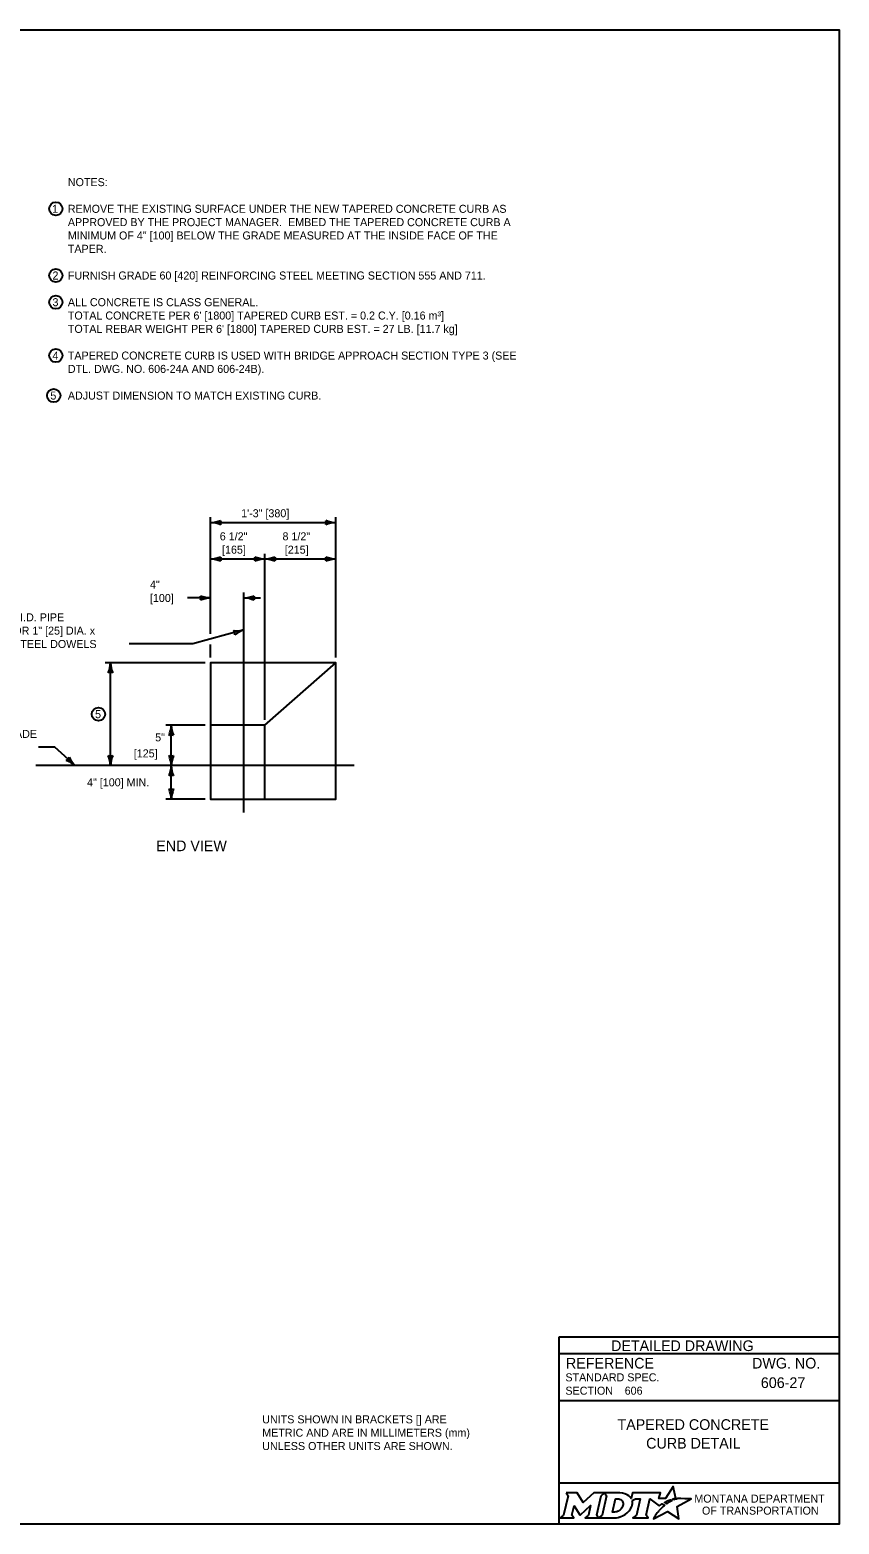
# Model space of a CAD drawing. Extents: x 49991.4 to 50021, y 49987.6 to 50011.4.
# Drawn here: x 50010.69 to 50016.75, y 49987.8 to 49999 of the extents above; entities that cross this region are included whole.
import ezdxf

# ---------------------------------------------------------------- set-up
doc = ezdxf.new("R2010")
doc.units = 0
for name, color, linetype in [('Default', 7, 'Continuous'), ('Level 1', 7, 'Continuous'), ('Level 2', 7, 'Continuous'), ('Level 3', 7, 'Continuous'), ('Level 4', 7, 'Continuous'), ('Level 5', 7, 'Continuous')]:
    doc.layers.add(name, color=color, linetype=linetype)

msp = doc.modelspace()

# ---------------------------------------------------------------- linework, layer by layer
at = {"layer": 'Default'}
for points in [[(50015.513, 49987.981), (50015.502, 49987.987), (50015.514, 49987.99), (50015.526, 49987.991), (50015.508, 49988.082), (50015.449, 49987.99), (50015.401, 49987.99), (50015.412, 49988.034), (50015.202, 49988.034), (50015.192, 49987.991), (50015.186, 49988)], [(50014.706, 49988.034), (50014.72, 49988.01), (50014.686, 49987.867), (50014.66, 49987.845), (50014.762, 49987.845), (50014.749, 49987.867), (50014.765, 49987.937), (50014.809, 49987.868), (50014.814, 49987.868), (50014.889, 49987.938), (50014.872, 49987.867), (50014.848, 49987.845), (50014.949, 49987.845), (50014.936, 49987.868), (50014.969, 49988.011)], [(50014.969, 49988.011), (50014.994, 49988.034), (50014.912, 49988.034), (50014.832, 49987.961), (50014.788, 49988.034), (50014.706, 49988.034)], [(50015.108, 49988.034), (50014.994, 49988.034), (50015.009, 49988.011), (50014.975, 49987.867), (50014.949, 49987.845), (50015.06, 49987.845)], [(50015.132, 49987.947), (50015.13, 49987.939), (50015.127, 49987.93), (50015.123, 49987.922), (50015.118, 49987.914), (50015.111, 49987.907), (50015.103, 49987.901), (50015.095, 49987.896), (50015.086, 49987.892), (50015.077, 49987.89), (50015.067, 49987.889), (50015.052, 49987.889), (50015.075, 49987.989), (50015.091, 49987.989), (50015.099, 49987.988), (50015.106, 49987.986), (50015.113, 49987.983), (50015.119, 49987.979), (50015.124, 49987.974), (50015.128, 49987.968), (50015.13, 49987.962), (50015.132, 49987.955), (50015.132, 49987.952), (50015.132, 49987.947)], [(50015.199, 49987.975), (50015.224, 49987.988), (50015.261, 49987.988), (50015.232, 49987.867), (50015.205, 49987.845), (50015.321, 49987.845), (50015.304, 49987.867), (50015.332, 49987.988), (50015.403, 49987.936), (50015.424, 49987.951), (50015.444, 49987.94)], [(50015.388, 49987.884), (50015.373, 49987.86), (50015.368, 49987.852), (50015.362, 49987.844), (50015.36, 49987.839), (50015.465, 49987.893), (50015.549, 49987.838), (50015.536, 49987.93), (50015.643, 49987.989), (50015.594, 49987.989), (50015.564, 49987.99), (50015.543, 49987.99), (50015.536, 49987.989), (50015.531, 49987.987), (50015.523, 49987.985), (50015.513, 49987.981)], [(50015.462, 49987.954), (50015.46, 49987.952), (50015.442, 49987.961), (50015.452, 49987.967), (50015.456, 49987.969), (50015.465, 49987.973), (50015.47, 49987.976), (50015.478, 49987.979), (50015.485, 49987.982), (50015.497, 49987.974), (50015.493, 49987.972), (50015.489, 49987.97), (50015.484, 49987.967), (50015.479, 49987.965), (50015.478, 49987.963), (50015.475, 49987.962), (50015.472, 49987.96), (50015.47, 49987.959), (50015.467, 49987.957), (50015.465, 49987.955), (50015.462, 49987.954)], [(50015.106, 49987.852), (50015.114, 49987.855), (50015.127, 49987.86), (50015.148, 49987.871)], [(50015.402, 49987.9), (50015.402, 49987.9)]]:
    msp.add_lwpolyline(points, dxfattribs=at)
for centre, radius, start, end in [((50015.131, 49987.955), 0.0709, 339.5329, 15.8582), ((50015.087, 49987.973), 0.118, 300.9103, 339.1383)]:
    msp.add_arc(centre, radius, start, end, dxfattribs=at)
for centre, major_axis, ratio, start_param, end_param in [((50015.106, 49987.986), (0.0834, -0.0037), 0.568097, 0.61298, 1.570796), ((50015.161, 49987.994), (0.0361, -0.0295), 0.469099, 1.225588, 1.570796), ((50015.06, 49987.993), (0, 0.148), 0.987302, 3.139398, 3.456847), ((50015.395, 49987.892), (-0.00694, -0.00806), 0.008222, 0, 3.137361), ((50015.412, 49987.911), (-0.0098, -0.0102), 0.016458, 3.141593, 6.279097), ((50015.433, 49987.93), (-0.0112, -0.0097), 0.021651, 3.157348, 6.283185)]:
    msp.add_ellipse(centre, major_axis=major_axis, ratio=ratio, start_param=start_param, end_param=end_param, dxfattribs=at)
at = {"layer": 'Level 1'}
for p, q in [((50012.449, 49993.787), (50012.981, 49994.255)), ((50012.449, 49993.787), (50012.042, 49993.787)), ((50012.449, 49993.484), (50012.449, 49993.787)), ((50013.117, 49993.484), (50010.732, 49993.484))]:
    msp.add_line(p, q, dxfattribs=at)
msp.add_lwpolyline([(49999.384, 49998.999), (50016.75, 49998.999), (50016.75, 49987.799), (49999.384, 49987.799)], close=True, dxfattribs=at)
msp.add_lwpolyline([(50012.981, 49993.484), (50012.981, 49994.255), (50012.042, 49994.255), (50012.042, 49993.484)], dxfattribs=at)
at = {"layer": 'Level 2'}
for centre in [(50010.883, 49997.658), (50010.883, 49997.158), (50010.883, 49996.958), (50010.883, 49996.558), (50010.867, 49996.258), (50011.202, 49993.87)]:
    msp.add_circle(centre, 0.05, dxfattribs=at)
at = {"layer": 'Level 3'}
for p, q in [((50012.042, 49994.472), (50012.042, 49995.346)), ((50012.981, 49994.295), (50012.981, 49995.346)), ((50012.042, 49995.306), (50012.981, 49995.306)), ((50012.449, 49995.033), (50012.042, 49995.033)), ((50012.449, 49993.827), (50012.449, 49995.073)), ((50012.981, 49995.033), (50012.449, 49995.033)), ((50012.042, 49994.741), (50011.869, 49994.741)), ((50012.292, 49994.741), (50012.416, 49994.741)), ((50012.292, 49994.501), (50011.908, 49994.396)), ((50011.908, 49994.396), (50011.432, 49994.396)), ((50012.042, 49994.295), (50012.042, 49994.392)), ((50012.002, 49994.255), (50011.252, 49994.255)), ((50011.292, 49993.484), (50011.292, 49994.255)), ((50012.002, 49993.787), (50011.708, 49993.787)), ((50011.748, 49993.484), (50011.748, 49993.787)), ((50010.876, 49993.622), (50010.752, 49993.622)), ((50011.028, 49993.484), (50010.876, 49993.622)), ((50011.748, 49993.233), (50011.748, 49993.484)), ((50012.002, 49993.233), (50011.708, 49993.233))]:
    msp.add_line(p, q, dxfattribs=at)
for centre, radius, start, end in [((50012.03, 49995.538), 0.233, 272.8273, 292.0772), ((50012.033, 49995.084), 0.222, 67.456, 87.6395), ((50012.17, 49995.306), 0.0548, 162.1388, 197.8612), ((50012.99, 49995.528), 0.222, 247.456, 267.6395), ((50012.853, 49995.306), 0.0548, 342.1388, 17.8612), ((50012.993, 49995.073), 0.233, 92.8273, 112.0772), ((50012.03, 49995.266), 0.233, 272.8273, 292.0772), ((50012.033, 49994.811), 0.222, 67.456, 87.6395), ((50012.17, 49995.033), 0.0548, 162.1388, 197.8612), ((50012.458, 49995.255), 0.222, 247.456, 267.6395), ((50012.321, 49995.033), 0.0548, 342.1388, 17.8612), ((50012.46, 49994.8), 0.233, 92.8273, 112.0772), ((50012.437, 49995.266), 0.233, 272.8273, 292.0772), ((50012.44, 49994.811), 0.222, 67.456, 87.6395), ((50012.577, 49995.033), 0.0548, 162.1388, 197.8612), ((50012.99, 49995.255), 0.222, 247.456, 267.6395), ((50012.853, 49995.033), 0.0548, 342.1388, 17.8612), ((50012.993, 49994.8), 0.233, 92.8273, 112.0772), ((50012.051, 49994.963), 0.222, 247.456, 267.6395), ((50011.914, 49994.741), 0.0548, 342.1388, 17.8612), ((50012.053, 49994.508), 0.233, 92.8273, 112.0772), ((50012.281, 49994.974), 0.233, 272.8273, 292.0772), ((50012.283, 49994.519), 0.222, 67.456, 87.6395), ((50012.421, 49994.741), 0.0548, 162.1388, 197.8612), ((50012.243, 49994.717), 0.222, 262.72, 282.9035), ((50012.169, 49994.467), 0.0548, 357.4028, 33.1251), ((50012.365, 49994.279), 0.233, 108.0913, 127.3411), ((50011.07, 49994.265), 0.222, 337.456, 357.6395), ((50011.525, 49994.267), 0.233, 182.8273, 202.0772), ((50011.292, 49994.127), 0.0548, 72.1388, 107.8612), ((50011.526, 49993.796), 0.222, 337.456, 357.6395), ((50011.98, 49993.799), 0.233, 182.8273, 202.0772), ((50011.748, 49993.659), 0.0548, 72.1388, 107.8612), ((50010.933, 49993.57), 0.0548, 300.0416, 335.764), ((50011.184, 49993.643), 0.222, 205.3588, 225.5423), ((50011.292, 49993.612), 0.0548, 252.1388, 287.8612), ((50011.059, 49993.472), 0.233, 2.8273, 22.0772), ((50011.514, 49993.475), 0.222, 157.456, 177.6395), ((50011.748, 49993.612), 0.0548, 252.1388, 287.8612), ((50011.515, 49993.472), 0.233, 2.8273, 22.0772), ((50011.97, 49993.475), 0.222, 157.456, 177.6395), ((50010.88, 49993.304), 0.233, 50.7301, 69.98), ((50011.526, 49993.493), 0.222, 337.456, 357.6395), ((50011.98, 49993.495), 0.233, 182.8273, 202.0772), ((50011.748, 49993.356), 0.0548, 72.1388, 107.8612), ((50011.748, 49993.362), 0.0548, 252.1388, 287.8612), ((50011.515, 49993.222), 0.233, 2.8273, 22.0772), ((50011.97, 49993.224), 0.222, 157.456, 177.6395)]:
    msp.add_arc(centre, radius, start, end, dxfattribs=at)
at = {"layer": 'Level 4'}
for points in [[(50012.042, 49993.484), (50012.042, 49993.233), (50012.449, 49993.233), (50012.449, 49993.484)], [(50012.449, 49993.233), (50012.981, 49993.233), (50012.981, 49993.484)]]:
    msp.add_lwpolyline(points, dxfattribs=at)
at = {"layer": 'Level 5'}
for p, q in [((50012.292, 49993.133), (50012.292, 49994.781)), ((50016.75, 49989.199), (50014.65, 49989.199)), ((50014.65, 49989.199), (50014.65, 49987.799)), ((50016.75, 49989.074), (50014.65, 49989.074)), ((50016.386, 49988.859), (50016.386, 49988.859)), ((50015.144, 49988.799), (50015.144, 49988.799)), ((50016.75, 49988.724), (50014.65, 49988.724)), ((50015.7, 49988.475), (50015.7, 49988.475)), ((50016.75, 49988.106), (50014.65, 49988.106))]:
    msp.add_line(p, q, dxfattribs=at)

# ---------------------------------------------------------------- texts
at = {"layer": 'Default'}
for s, p in [('MONTANA DEPARTMENT', (50015.666, 49987.96)), ('OF TRANSPORTATION', (50015.723, 49987.87))]:
    msp.add_text(s, height=0.06, dxfattribs=at).set_placement(p)
at = {"layer": 'Level 2'}
for s, height, p in [('NOTES:', 0.06, (50010.973, 49997.828)), ('1', 0.06, (50010.855, 49997.628)), ('APPROVED BY THE PROJECT MANAGER.  EMBED THE TAPERED CONCRETE CURB A', 0.06, (50010.973, 49997.528)), ('REMOVE THE EXISTING SURFACE UNDER THE NEW TAPERED CONCRETE CURB AS', 0.06, (50010.973, 49997.628)), ('MINIMUM OF 4" [100] BELOW THE GRADE MEASURED AT THE INSIDE FACE OF THE ', 0.06, (50010.973, 49997.428)), ('TAPER.', 0.06, (50010.973, 49997.328)), ('2', 0.06, (50010.858, 49997.128)), ('FURNISH GRADE 60 [420] REINFORCING STEEL MEETING SECTION 555 AND 711.', 0.06, (50010.973, 49997.128)), ('3', 0.06, (50010.858, 49996.928)), ('ALL CONCRETE IS CLASS GENERAL.  ', 0.06, (50010.973, 49996.928)), ("TOTAL CONCRETE PER 6' [1800] TAPERED CURB EST. = 0.2 C.Y. [0.16 m³]", 0.06, (50010.973, 49996.828)), ("TOTAL REBAR WEIGHT PER 6' [1800] TAPERED CURB EST. = 27 LB. [11.7 kg]", 0.06, (50010.973, 49996.728)), ('4', 0.06, (50010.858, 49996.528)), ('TAPERED CONCRETE CURB IS USED WITH BRIDGE APPROACH SECTION TYPE 3 (SEE', 0.06, (50010.973, 49996.528)), ('DTL. DWG. NO. 606-24A AND 606-24B).', 0.06, (50010.973, 49996.428)), ('5', 0.06, (50010.842, 49996.228)), ('ADJUST DIMENSION TO MATCH EXISTING CURB.', 0.06, (50010.973, 49996.228)), ('1\'-3" [380]', 0.06, (50012.271, 49995.346)), ('6 1/2"', 0.06, (50012.111, 49995.173)), ('8 1/2"', 0.06, (50012.581, 49995.173)), ('[165]', 0.06, (50012.128, 49995.073)), ('[215]', 0.06, (50012.598, 49995.073)), ('4"', 0.06, (50011.588, 49994.811)), ('[100]', 0.06, (50011.588, 49994.711)), ('¡ 1 1/2" [38] I.D. PIPE', 0.06, (50010.181, 49994.566)), ('SLEEVE FOR 1" [25] DIA. x', 0.06, (50010.181, 49994.466)), ('3\'-0" [915] STEEL DOWELS', 0.06, (50010.181, 49994.366)), ('5', 0.06, (50011.177, 49993.84)), ('FINISHED GRADE', 0.06, (50010.06, 49993.692)), ('5"', 0.06, (50011.627, 49993.666)), ('[125]', 0.06, (50011.467, 49993.546)), ('4" [100] MIN.', 0.06, (50011.117, 49993.329)), ('END VIEW', 0.08, (50011.635, 49992.843)), ('606-27', 0.08, (50016.164, 49988.819)), ('606', 0.06, (50015.144, 49988.769)), ('UNITS SHOWN IN BRACKETS [] ARE ', 0.06, (50012.429, 49988.554)), ('METRIC AND ARE IN MILLIMETERS (mm) ', 0.06, (50012.429, 49988.454)), ('TAPERED CONCRETE', 0.08, (50015.09, 49988.505)), ('UNLESS OTHER UNITS ARE SHOWN.', 0.06, (50012.429, 49988.354)), ('CURB DETAIL', 0.08, (50015.305, 49988.365))]:
    msp.add_text(s, height=height, dxfattribs=at).set_placement(p)
at = {"layer": 'Level 5'}
for s, height, p in [('DETAILED DRAWING', 0.0799, (50015.042, 49989.096)), ('REFERENCE', 0.08, (50014.704, 49988.965)), ('DWG. NO.', 0.08, (50016.098, 49988.965)), ('STANDARD SPEC.', 0.06, (50014.7, 49988.869)), ('SECTION', 0.06, (50014.7, 49988.769))]:
    msp.add_text(s, height=height, dxfattribs=at).set_placement(p)

doc.saveas('drawing.dxf')
